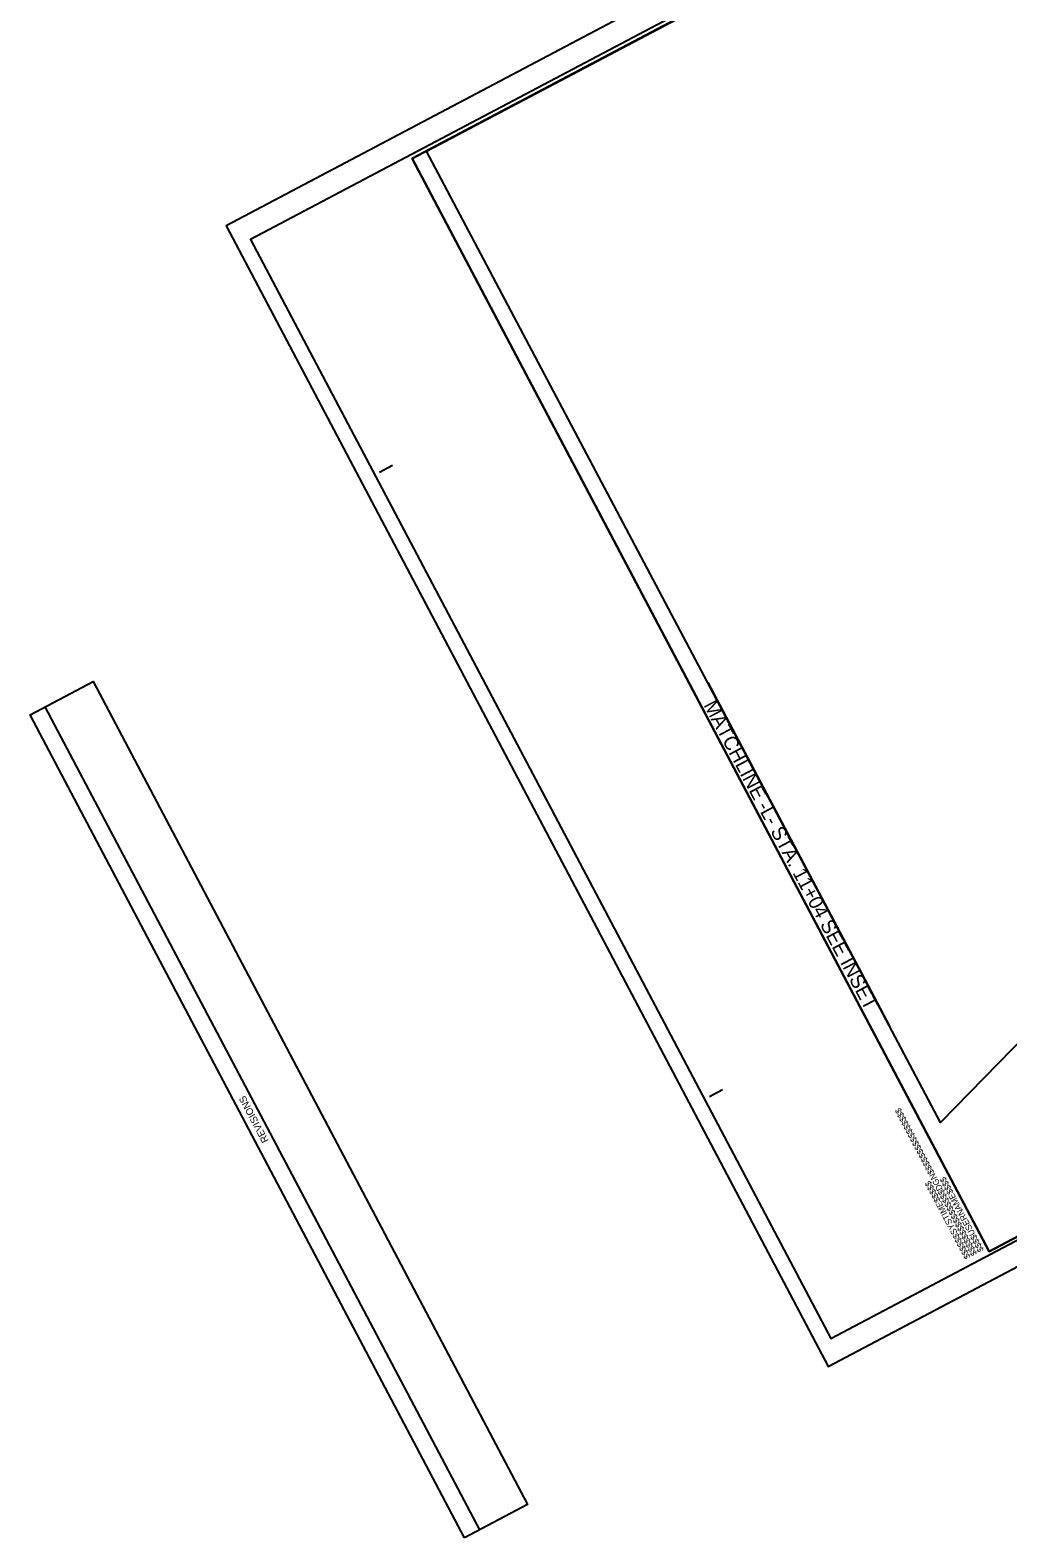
# Model space of a CAD drawing. Extents: x 1487165 to 1493546, y 497841 to 501709.
# Drawn here: x 1487176 to 1488007, y 497841 to 499122 of the extents above; entities that cross this region are included whole.
import ezdxf

# ---------------------------------------------------------------- set-up
doc = ezdxf.new("R2010")
doc.units = 0
for name, color, linetype in [('Matchline', 7, 'Continuous'), ('Matchline Text', 7, 'Continuous'), ('Prop Text', 7, 'Continuous'), ('Scratch_Level_3', 7, 'Continuous'), ('Sheet Block Revision CELL', 7, 'Continuous'), ('Sheet Block Title CELL', 7, 'Continuous'), ('Sheet Clip Boundary CELL', 7, 'Continuous'), ('Sheet Plan CELL', 7, 'Continuous'), ('Sheet Plot Border Inside CELL', 7, 'Continuous'), ('Sheet Plot Border Outside CELL', 7, 'Continuous')]:
    doc.layers.add(name, color=color, linetype=linetype)

msp = doc.modelspace()

# ---------------------------------------------------------------- linework, layer by layer
at = {"layer": 'Matchline'}
msp.add_line((1487751.6, 498568.2), (1487906.2, 498276.2), dxfattribs=at)
at = {"layer": 'Scratch_Level_3'}
msp.add_lwpolyline([(1487512.6, 499019.7), (1488662.1, 499625.8), (1488771.2, 499418.9), (1488936.6, 499506), (1489317.2, 498785.2), (1488242.7, 498217.8), (1488120.4, 498369.2), (1487949.5, 498194.2)], close=True, dxfattribs=at)
at = {"layer": 'Sheet Block Revision CELL'}
msp.add_line((1487557.9, 497848.3), (1487188.7, 498547.4), dxfattribs=at)
msp.add_lwpolyline([(1487545, 497841.5), (1487175.9, 498540.6), (1487229.4, 498568.9), (1487598.6, 497869.7)], close=True, dxfattribs=at)
at = {"layer": 'Sheet Block Title CELL'}
msp.add_lwpolyline([(1488826.9, 499713.7), (1487500.5, 499013.3), (1487990.8, 498084.8), (1489317.2, 498785.2)], close=True, dxfattribs=at)
at = {"layer": 'Sheet Clip Boundary CELL'}
msp.add_lwpolyline([(1487500.5, 499013.2), (1488662.1, 499625.8), (1488771.2, 499418.9), (1488936.6, 499506), (1489317.2, 498785.1), (1487990.8, 498084.7)], close=True, dxfattribs=at)
at = {"layer": 'Sheet Plan CELL'}
for p, q in [((1487856.2, 498010.8), (1487856.2, 498010.8)), ((1487854.1, 497987.1), (1487854.1, 497987.1))]:
    msp.add_line(p, q, dxfattribs=at)
at = {"layer": 'Sheet Plot Border Inside CELL'}
for p, q in [((1487472.7, 498746.9), (1487483.8, 498752.8)), ((1487753.1, 498216.5), (1487764.2, 498222.3))]:
    msp.add_line(p, q, dxfattribs=at)
msp.add_lwpolyline([(1488835.9, 499722.2), (1487363.2, 498944.6), (1487856.2, 498010.8), (1489329, 498788.5)], close=True, dxfattribs=at)
at = {"layer": 'Sheet Plot Border Outside CELL'}
msp.add_lwpolyline([(1488830.6, 499742), (1487342.4, 498956.2), (1487854.1, 497987.1), (1489342.3, 498772.9)], close=True, dxfattribs=at)

# ---------------------------------------------------------------- texts
at = {"layer": 'Matchline Text'}
msp.add_text('MATCHLINE -L- STA. 11+04 SEE INSET', height=12, rotation=297.9716, dxfattribs=at).set_placement((1487747.8, 498549))
at = {"layer": 'Prop Text'}
for s, p in [('$$$$$$$$$$$$$$$$DGN$$$$$$$$$$$$$$$$', (1487980.7, 498082.8)), ('$$$$$$SYSTIME$$$$$', (1487975, 498080)), ('$$$$USERNAME$$$$', (1487986.4, 498085.9))]:
    msp.add_text(s, height=5.25, rotation=117.8351, dxfattribs=at).set_placement(p)
at = {"layer": 'Sheet Block Revision CELL'}
msp.add_text('REVISIONS', height=6, rotation=117.8351, dxfattribs=at).set_placement((1487378.7, 498179))

doc.saveas('drawing.dxf')
